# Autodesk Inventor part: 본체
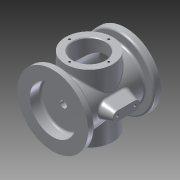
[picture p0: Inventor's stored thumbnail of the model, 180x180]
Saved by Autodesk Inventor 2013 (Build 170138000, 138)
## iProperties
Created: 2018-02
Part Number: 본체
Material: 알루미늄 6061
Document SubType Name: Modeling
Designer: Administrator
Density: 2.71 g/cm^3
Mass: 834.201 g
Surface Area: 812.252 cm^2
Volume: 307.823 cm^3
Author: Administrator
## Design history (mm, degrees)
sketch "스케치2"
  geometry: C1 r 38 at (0, 0); 1 further point
  constraints: 1 centre point, 1 coincident
  dimensions: "d0" = 38 radius of C1
extrude "돌출1" new body sketch "스케치2" stored distance "d1" = 108; taper "d2" = 0 deg
sketch "스케치3"
  geometry: C1 r 52.5 at (0, 0); 1 further point
  constraints: 1 centre point, 1 coincident
  dimensions: "d3" = 52.5 radius of C1
extrude "돌출2" join sketch "스케치3" distance "d4" = 10; taper "d5" = 0 deg
hole "구멍1" diameter "d8" = 66; stored, may be unused: countersink angle "d12" = 90 deg, drill point angle "d14" = 0 deg; dims "d9" = 6, "d10" = 74, "d11" = 7, "d13" = 86, "d113" = 10, "d114" = 10
sketch "스케치5" dims "d17" = 45
  geometry: 3 further points
  constraints: 2 vertical alignment, 1 coincident, 2 other
hole "구멍2" sketch "스케치5" at (0, 45) diameter "d18" = 3.242; stored, may be unused: countersink angle "d22" = 90 deg, drill point angle "d24" = 118 deg; dims "d19" = 4, "d20" = 90, "d21" = 7, "d23" = 6
hole "구멍3" diameter "d30" = 68; stored, may be unused: countersink angle "d34" = 90 deg, drill point angle "d36" = 0 deg; dims "d31" = 4, "d32" = 90, "d33" = 7, "d35" = 16, "d37" = 10, "d38" = 10
hole "구멍4" diameter "d41" = 10; stored, may be unused: countersink angle "d45" = 90 deg, drill point angle "d47" = 118 deg; dims "d39" = 10, "d40" = 10, "d42" = 4, "d43" = 90, "d44" = 7, "d46" = 16
node "작업 평면1"
sketch "스케치6"
  geometry: C1 r 35 at (0, 0); 1 further point
  constraints: 1 centre point, 1 coincident
  dimensions: "d49" = 35 radius of C1
extrude "돌출3" join sketch "스케치6" stored distance "d50" = 10; taper "d51" = 0 deg
hole "구멍5" diameter "d54" = 48; stored, may be unused: countersink angle "d58" = 90 deg, drill point angle "d60" = 118 deg; dims "d52" = 10, "d53" = 10, "d55" = 4, "d56" = 90, "d57" = 7, "d59" = 16
sketch "스케치7" dims "d61" = 29
  geometry: 3 further points
  constraints: 2 vertical alignment, 1 coincident, 2 other
hole "구멍6" sketch "스케치7" at (0, 29) diameter "d62" = 3.242; stored, may be unused: countersink angle "d66" = 90 deg, drill point angle "d68" = 118 deg; dims "d63" = 4, "d64" = 90, "d65" = 7, "d67" = 6
chamfer "모따기1" distance "d72" = 1; stored, may be unused: second distance "d73" = 2, angle "d74" = 45 deg
node "작업 평면2"
sketch "스케치8"
  geometry: L1 (20, 0)-(-20, 0); L2 (13, 7)-(-13, 7); L3 (-13, -7)-(13, -7); A1 r 7 centre (13, 0) between (13, -7) and (13, 7); A2 r 7 centre (-13, 0) between (-13, 7) and (-13, -7); 2 further points
  constraints: 6 end point, 6 point on circle, 4 tangent, 2 centre point, 2 coincident, 2 horizontal alignment, 1 horizontal, 1 midpoint
  dimensions: "d76" = 7 radius of A1; "d77" = 7 radius of A2; "d79" = 40 distance of L1.start L1.end
extrude "돌출4" join sketch "스케치8" stored distance "d80" = 10; taper "d81" = 15 deg
hole "구멍7" diameter "d84" = 4.134; stored, may be unused: countersink angle "d88" = 90 deg, drill point angle "d90" = 118 deg; dims "d82" = 10, "d83" = 10, "d85" = 6, "d86" = 90, "d87" = 7, "d89" = 8
hole "구멍8" diameter "d93" = 4.134; stored, may be unused: countersink angle "d97" = 90 deg, drill point angle "d99" = 118 deg; dims "d91" = 10, "d92" = 10, "d94" = 6, "d95" = 90, "d96" = 7, "d98" = 8
fillet "모깎기1" dims "d100" = 3
chamfer "모따기2" distance "d101" = 1; stored, may be unused: second distance "d102" = 2, angle "d103" = 45 deg
fillet "모깎기2" dims "d104" = 3
fillet "모깎기3" dims "d105" = 3
fillet "모깎기4" dims "d106" = 3
fillet "모깎기5" dims "d107" = 3
sketch "스케치9"
  geometry: C1 r 43 at (0, 0); 1 further point
  constraints: 1 centre point, 1 coincident, 1 other
  dimensions: "d108" = 43 radius of C1
feature "엠보싱1" sketch "스케치9" dims "d1" = 108, "d25" = 40, "d111" = 0.5, "d112" = 0
fillet "모깎기6" dims "d115" = 3
node "솔리드1"
mirror "대칭1"
pattern_circular "원형 패턴1" dims angle "d26" = 360 deg
pattern_circular "원형 패턴2" dims angle "d70" = 360 deg
mirror "대칭2"
other parameters: "d75" = 55
